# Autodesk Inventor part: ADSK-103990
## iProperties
Shininess: 0.0
Created: 2000-11
Part Number: ADSK-103990
Description: Sproket H60P20 Bore = 1-1/2" c/w KEYWAY
Document SubType Name: Modeling
Stock Number: ADSK-103990
Density: 1 g/cm^3
Density: 0.0
Volumn: 0.0
Area: 0.0
PropertySet Name: Model Information
Control State: 0
Master: False
Checked Out: False
Author: gao
